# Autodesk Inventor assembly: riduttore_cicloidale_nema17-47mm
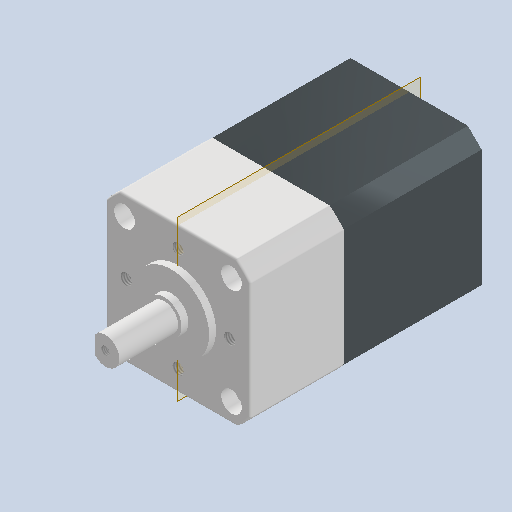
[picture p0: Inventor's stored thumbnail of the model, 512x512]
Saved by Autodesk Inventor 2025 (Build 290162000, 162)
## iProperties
Created: 2026-03
Part Number: riduttore_cicloidale_nema17-47mm
Document SubType Name: Assembly
Designer: R5800u
Author: R5800u
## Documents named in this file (3)
- C:\Users\Ryzen5700u\Desktop\robot_cicloidale_singolo\Workgroups\NotInProject\riduttore_cicloidale_nema17-47mm.iam
- C:\Users\Ryzen5700u\Desktop\robot_cicloidale_singolo\Workgroups\NotInProject\NEMA 17.ipt
- C:\Users\Ryzen5700u\Desktop\robot_cicloidale_singolo\Workgroups\NotInProject\riduttore ciccloidale TS42 15-1.ipt
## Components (2 placed, 2 different names)
1. NEMA 17:1 — Coincidente:1, Coincidente:2, Angolo:1
2. riduttore ciccloidale TS42 15-1:1 — Coincidente:1, Coincidente:2, Angolo:1
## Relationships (3: Mate 2, Angle 1)
- Coincidente:1 [Mate]: NEMA 17:1 ↔ riduttore ciccloidale TS42 15-1:1
- Coincidente:2 [Mate]: NEMA 17:1 ↔ riduttore ciccloidale TS42 15-1:1
- Angolo:1 [Angle]: NEMA 17:1 ↔ riduttore ciccloidale TS42 15-1:1
